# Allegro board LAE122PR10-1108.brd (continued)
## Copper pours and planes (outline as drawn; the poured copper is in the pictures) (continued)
GNDA on GND2: 283.19,30.43 280.19,33.43 280.19,44.92 271.57,53.54 269.5,53.54 265.25,49.29 251.1,49.29 251.1,56.41 249.83,57.68 249.83,61.4 251.1,62.67 251.1,63.05 251.18,63.13 254.2,63.13 254.72,62.61 254.72,57.73 258.41,57.73 258.41,56.99 258.34,56.92 258.34,56.76 259.48,55.62 259.48,53.78 259.85,53.41 262.42,53.41 262.79,53.78 262.79,56.41 262.48,56.72 261.28,56.72 261.14,56.86 261.14,58.26 261.02,58.37 260.93,58.37 260.81,58.49 259.93,58.49 259.93,59.38 260.9,59.38 261.14,59.19 261.14,59.11 261.25,59 261.69,59 262.14,58.56 266.2,58.56 267.34,57.41 273.25,57.41 283.66,47 294.52,47 295.43,46.09 295.4,46 295.39,45.9 295.39,43.5 295.54,43.14 295.9,42.99 299,42.99 299.21,42.91 299.29,42.7 299.29,40.75 299.21,40.54 299,40.46 286.6,40.46 285.9,39.85 286.39,39.07 286.39,33.63 285.9,32.85 286.6,32.24 299,32.24 299.21,32.16 299.29,31.95 299.29,30.43
VCCSA_B+ on TOP (solid shape): 65.17,113.78 65.02,113.63 63.93,113.63 63.78,113.78 63.78,115.02 65.17,115.02
VCCSA_B+ on BOTTOM (solid shape): 65.64,114.54 68.35,114.54 68.35,114.01 67.73,114.01 67.64,113.92 67.64,112.91 67.38,112.66 64.49,112.66 64.49,113.22 63.96,113.22 63.96,112.66 63.73,112.66 63.73,114.96 63.78,115.01 65.17,115.01
VIN_1.8VALW on BOTTOM (solid shape): 170.81,67.3 170.81,66.51 171.27,66.05 171.27,65.75 171.07,65.54 170.38,65.54 168.4,67.52 168.4,67.55 169.11,68.26 169.85,68.26
VIN_1V_PRIM on TOP (solid shape): 161.22,129.49 161.22,129.17 161.41,128.98 161.98,128.98 162.04,128.92 162.04,128.41 161.98,128.34 160.2,128.34 160.08,128.47 160.08,129.49 160.2,129.61 161.09,129.61
VIN_1V_PRIM on BOTTOM (solid shape): 161.19,129.49 161.19,129.11 161.31,128.98 161.95,128.98 162.01,128.92 162.01,128.07 161.92,127.98 161.3,127.98 161.01,127.68 161.01,126.6 160.91,126.5 159.41,126.5 158.58,127.33 158.58,128.53 158.71,128.66 159.6,128.66 159.92,128.98 159.92,129.49 160.04,129.61 161.06,129.61
VIN_1VS_VCCIO on TOP (solid shape): 145.25,131.01 145.25,130.69 145.5,130.44 146.07,130.44 146.07,129.93 146.01,129.87 144.23,129.87 144.17,129.93 144.17,130.95 144.3,131.07 145.18,131.07
VIN_1VS_VCCIO on BOTTOM (solid shape): 145.31,130.95 145.31,130.63 145.44,130.5 146.01,130.5 146.07,130.44 146.07,129.74 145.95,129.61 145.22,129.61 144.98,129.38 144.98,128.03 143.53,128.03 142.71,128.85 142.71,130.06 142.84,130.19 143.72,130.19 144.04,130.5 144.04,130.95 144.17,131.07 145.18,131.07
+AC_IN on TOP (solid shape): 48.89,105.5 48.89,103.8 48.77,103.67 48.18,103.67 47.47,102.96 45.46,102.96 45.44,102.98 45.44,103.44 45.3,103.58 45.3,105.04 45.31,105.05 45.31,105.34 45.62,105.65 48.74,105.65
+AC_IN on TOP (solid shape): outline of 300 points within 29.68,112.42 43.71,120.6
+AC_IN on BOTTOM (solid shape): 47.04,104.47 47.04,103.4 46.75,103.11 45.69,103.11 45.52,102.93 45.52,102.35 45.13,101.97 43.24,101.97 43.15,102.06 43.15,103.36 43.27,103.48 44.26,103.48 45.34,104.56 46.95,104.56
+AC_IN on IN2 (solid shape): 39.9,115.64 41.62,115.64 41.81,115.45 41.81,113.42 41.62,113.23 35.65,113.23 33.3,115.58 32.28,115.58 32.09,115.77 32.09,117.68 32.41,117.99 37.55,117.99
+AC_IN on VCC: 45.4,103.39 39.77,109.02 39.77,115.16 40.52,115.9 45.26,115.9 48.47,112.68 48.47,104.07 47.8,103.39
+BL_PWR_SRC on TOP (solid shape): 48.25,128.5 48.25,128.05 46.51,126.31 46.51,122.12 46.38,121.99 45.11,121.99 44.98,122.12 44.98,126.17 45.08,126.27 45.08,127.16 47.03,129.11 47.64,129.11
+BL_PWR_SRC on TOP (solid shape): 58.02,133.22 58.94,133.22 59.3,132.85 60.79,132.85 60.98,132.66 60.98,131.9 60.5,131.42 58.89,131.42 58.59,131.71 57.68,131.71 57.2,132.19 56.52,132.19 56.43,132.28 56.43,133.76 56.54,133.87 57.36,133.87
+BL_PWR_SRC on BOTTOM (solid shape): 60.37,133.28 60.37,132 60.54,131.84 60.54,131.39 60.41,131.27 59.12,131.27 58.89,131.5 58.89,131.79 59.13,132.03 59.13,133.28 59.21,133.36 60.3,133.36
+CHARGER_SRC on TOP (solid shape): 47.97,79.39 49.24,79.39 49.55,79.07 49.55,72.78 49.11,72.34 47.01,72.34 46.63,71.96 46.63,71.38 46.19,71.38 46.19,75.51 45.81,75.89 45.81,79.83 45.55,80.08 45.55,80.67 45.59,80.71 46.65,80.71
+CHARGER_SRC on BOTTOM (solid shape): 49.24,84.02 48.66,84.02 48.66,81.99 49.24,81.99 49.24,80.21 49.93,79.51 50.89,79.51 50.89,73.54 50.82,73.48 46.06,73.48 45.81,73.73 45.81,79.83 45.55,80.08 45.55,84.15 45.81,84.4 48.37,84.4 48.47,84.5 49.24,84.5
+DC_IN on BOTTOM (solid shape): 46.89,121.11 47.33,120.66 47.33,118.5 47.23,118.4 43.59,118.4 43.53,118.4 43.46,118.4 42.63,118.4 42.63,118.38 41.87,118.38 41.74,118.5 41.74,119.26 41.81,119.33 42.51,119.33 42.89,119.71 42.89,121.17 43.39,121.68 46.89,121.68
+DC_IN_SS on BOTTOM (solid shape): 52.78,118.71 52.78,117.33 52.63,117.18 49.58,117.18 48.94,116.55 48.94,113.24 48.77,113.07 44.78,113.07 44.5,113.25 44.17,113.16 44.13,113.13 43.89,113.37 43.89,115.4 44.17,115.68 44.17,116.32 44.83,116.98 44.83,117.59 45.01,117.77 47.55,117.77 48.7,118.92 52.57,118.92
+DCIN_JACK on BOTTOM (solid shape): 41.92,121.74 42.01,121.71 42.09,121.69 42.11,121.69 42.31,121.49 42.31,119.84 42.06,119.58 41.74,119.58 41.49,119.33 41.49,118.44 41.3,118.25 39.27,118.25 39.09,118.07 36.71,118.07 36.47,118.31 36.47,121.4 36.82,121.74 41.84,121.74
+EC_DEBUG_VCC on BOTTOM (solid shape): 289.57,127.46 289.95,127.46 290.61,126.8 291.11,126.8 291.32,126.59 291.32,126.29 291.23,126.2 289.93,126.2 289.74,126.39 289.19,126.39 288.86,126.73 288.86,127.37 288.95,127.46 289.57,127.46
+EDP_VDD on TOP (solid shape): 67.97,126.95 67.97,124.92 67.65,124.6 66.7,124.6 66.52,124.78 66.52,125.61 65.86,126.27 65.86,127.71 67.21,127.71
+LCDVDD on TOP (solid shape): 66.19,132.26 66.19,130.95 65.95,130.7 65.95,128.29 65.68,128.03 65.68,127.46 65.11,127.46 65.11,126.95 65.68,126.95 65.68,126.69 64.6,126.69 64.41,126.88 64.41,131.14 64.86,131.59 64.86,132.41 66.04,132.41
+LCDVDD on BOTTOM (solid shape): 66.38,133.3 66.38,132.03 66.57,131.84 66.57,131.2 66.13,130.76 66.13,129.74 66,129.61 64.79,129.61 64.67,129.74 64.67,131.58 64.92,131.84 65.43,131.84 65.62,132.03 65.62,133.3 65.68,133.36 66.32,133.36
+PBATT on TOP (solid shape): outline of 107 points within 170.2,55.26 177.96,60.78
+PWR_SRC on TOP (solid shape): 44.54,123.33 44.54,121.93 44.28,121.68 42.05,121.68 41.89,121.84 41.89,122.24 41.88,122.33 41.85,122.43 41.85,123.05 41.92,123.13 43.57,123.13 43.9,123.45 44.41,123.45
+PWR_SRC on TOP (solid shape): 171.22,53.35 171.22,52.41 170.69,52.41 170.67,52.39 170.65,52.38 170.34,52.03 170.65,51.68 170.67,51.67 170.69,51.65 171.14,51.65 171.17,51.62 171.17,50.19 170.84,49.86 164.74,49.86 164.43,50.18 164.43,52.75 165.34,53.67 170.9,53.67
+PWR_SRC on TOP (solid shape): 71.59,81.1 74.76,81.1 75.59,80.27 75.59,76.27 75.14,75.83 73.56,75.83 72.32,77.06 64.34,77.06 63.69,76.41 63.69,74.28 63.51,74.11 63.37,74.01 63.27,73.87 63.27,73.86 62.57,73.16 62.57,66.75 62.13,66.3 58.7,66.3 58.7,65.35 58.25,65.35 58.25,69.61 58.82,70.18 58.83,70.33 58.83,76.78 59.02,76.97 59.02,80.08 60.48,81.54 71.14,81.54
+PWR_SRC on BOTTOM (solid shape): 181.36,50.94 183.9,50.94 184,50.84 184,49.84 184.25,49.59 184.25,49.54 184.05,49.34 180.16,49.34 179.98,49.52 179.98,50.31 180.62,50.94 181.36,50.94
+PWR_SRC on BOTTOM (solid shape): 39.01,130.57 39.01,129.75 38.75,129.13 39.36,128.85 39.39,128.86 43.75,124.49 43.75,122.28 43.46,121.99 41.94,121.99 41.84,122.09 41.85,122.12 41.86,122.29 41.81,122.46 41.81,124.09 39.14,126.76 39.14,127.52 37.87,128.79 37.87,130.5 38.06,130.69 38.89,130.69
+PWR_SRC on BOTTOM (solid shape): outline of 1686 points within 57.97,49.86 169,82.82
+PWR_SRC on IN1 (solid shape): outline of 167 points within 164.36,49.34 182.47,52.87
+PWR_SRC on IN2 (solid shape): 45.44,122.31 45.44,121.04 45.27,120.86 42.26,120.86 41.87,121.26 41.87,122.31 42,122.44 45.31,122.44
+PWR_SRC on IN2 (solid shape): 58.32,119.24 58.32,118.53 58.71,118.13 58.71,117.44 58.52,117.24 57.28,117.24 56.68,117.84 56.68,118.69 56.46,118.91 56.46,119.87 56.59,120 57.55,120
+PWR_SRC on IN3 (solid shape): 58.74,118.06 58.74,116.52 58.58,116.37 57.24,116.37 57.24,118.06 57.36,118.18 58.61,118.18
+PWR_SRC on IN3 (solid shape): 58.76,81.99 58.76,80.4 58.57,80.21 57.43,80.21 56.86,80.78 56.86,82.31 57.43,82.88 57.87,82.88
+PWR_SRC on IN3 (solid shape): outline of 190 points within 164.36,49.34 182.47,52.08
+PWR_SRC_AC on TOP (solid shape): 54.13,84.15 54.13,80.53 53.81,80.21 50.63,80.21 50.44,80.4 50.44,82.93 50.98,82.93 51.33,83.28 50.98,83.64 50.44,83.64 50.44,84.34 50.57,84.47 53.81,84.47
+PWR_SRC_AC on BOTTOM (solid shape): 49.72,84.4 53.49,84.4 54,83.89 54,80.53 53.68,80.21 49.81,80.21 49.43,80.59 49.43,84.5 49.62,84.5
+REGCTL_PNP10 on TOP (solid shape): 246.58,123.43 246.58,122.08 246.91,121.75 246.91,121.09 246.78,120.97 246.3,120.97 246.18,121.09 246.18,121.57 246.25,121.77 246.18,121.96 246.18,122.16 246.38,122.36 246.38,123.43 246.43,123.48 246.53,123.48
+REGCTL_PNP10 on BOTTOM (solid shape): 252.25,125.32 252.25,124.28 251.8,123.84 250.85,123.84 250.51,124.18 250.51,125.26 250.67,125.42 252.14,125.42
+REGCTL_PNP10 on IN3 (solid shape): 251.61,124.55 251.61,123.76 250.42,122.57 247.86,122.57 247.1,121.8 247.1,121.04 246.91,120.85 246.15,120.85 245.83,121.17 245.83,122.57 247.31,124.04 250.08,124.04 250.22,124.18 250.23,124.18 250.4,124.28 250.5,124.45 250.5,124.47 250.76,124.72 251.43,124.72
+RTC_CELL on TOP (solid shape): outline of 308 points within 119.76,89.76 124.68,97.88
+SDC_IN on TOP (solid shape): 52.35,111.45 52.35,109.48 52.03,109.17 50.25,109.17 50.06,109.36 50.06,109.93 49.87,110.12 48.79,110.12 48.66,109.99 48.66,109.36 47.2,109.36 47.14,109.42 47.14,111.2 47.97,112.02 51.78,112.02
+SDC_IN on TOP (solid shape): 51.33,86.43 51.33,84.91 51.14,84.72 50.19,84.72 49.43,83.96 49.43,83.67 48.89,83.67 48.86,83.64 48.85,83.64 48.54,83.28 48.85,82.93 48.86,82.93 48.89,82.9 49.32,82.9 49.35,82.87 49.35,82.18 46.7,82.18 45.81,83.07 45.81,86.12 46.32,86.62 51.14,86.62
+SDC_IN on BOTTOM (solid shape): 52.75,116.39 52.75,111.57 51.95,111.57 51.59,111.2 51.59,110.4 51.01,109.83 51.01,105.23 47.71,105.23 47.71,106.42 47.7,106.44 47.7,106.79 47.42,107.07 46.23,107.07 45.74,106.59 45.21,106.59 44.98,106.82 44.98,107.63 45.21,107.86 46,107.86 46.23,108.09 46.23,108.6 45.97,108.85 44.91,108.85 44.7,108.65 44.04,108.65 44.04,109.18 44.12,109.26 45.83,109.26 46.06,109.48 46.06,110.06 46.44,110.44 46.44,111.2 46.23,111.42 46.23,112.32 46.32,112.41 48.73,112.41 49.43,113.1 49.43,116.41 49.49,116.47 52.68,116.47
+SDC_IN on IN2 (solid shape): outline of 2338 points within 45.68,84.4 56.79,111.9
+SDREG2 on TOP (solid shape): 279,67.88 279.09,67.79 279.09,67.13 279.02,67.05 278.52,67.05 277.77,66.3 277.77,66.23 277.71,66.16 276.93,66.16 276.87,66.23 276.87,66.31 276.93,66.38 277.09,66.38 277.96,67.26 277.96,67.63 278.22,67.88 278.81,67.88
+TBTA_VBUS on TOP (solid shape): 24.15,116.79 24.15,114.06 23.84,113.74 23.39,113.74 23.14,113.49 23.14,112.91 20.47,112.91 19.52,113.87 16.79,113.87 16.41,114.25 16.41,116.6 16.72,116.91 24.03,116.91
+TBTA_VBUS on TOP (solid shape): 7.29,108.57 8.38,108.57 8.47,108.66 9.76,108.66 9.85,108.57 9.85,108.24 9.78,108.16 8.43,108.16 8.36,108.24 7.16,108.24 7.09,108.16 6.4,108.16 6.27,108.29 6.27,108.67 6.45,108.85 7.01,108.85
+TBTA_VBUS on TOP (solid shape): 7.14,106.06 8.38,106.06 8.47,106.14 9.5,106.14 9.57,106.07 9.57,105.73 9.5,105.65 8.43,105.65 8.36,105.73 7.16,105.73 6.88,105.45 6.42,105.45 6.3,105.57 6.3,106.03 6.42,106.16 7.03,106.16
+TBTA_VBUS on BOTTOM (solid shape): 10.06,105.93 10.06,104.91 9.23,104.91 8.48,105.66 8.48,105.99 8.6,106.11 9.88,106.11
+TBTA_VBUS on IN2 (solid shape): outline of 315 points within 6.32,105.42 22.82,116.6
+TBTA_VBUS on VCC: 6.32,105.42 6.32,108.91 7.88,108.91 8.66,109.7 8.66,111.22 11.43,113.99 13.15,113.99 14.82,115.67 14.82,116.93 22.25,116.93 22.25,114.42 21.95,114.12 20.87,114.12 16.62,109.87 13.89,109.87 12.41,108.38 12.41,105.4 12.3,105.29 7.64,105.29 7.52,105.42
+TBTA_VBUS_1 on TOP (solid shape): 29.11,118.86 29.61,118.35 29.61,113.17 29.36,112.91 27.5,112.91 27.49,112.92 27.13,112.92 27.13,112.91 25.8,112.91 25.8,113.55 25.68,113.68 25.17,113.68 25.04,113.8 25.04,116.85 25.23,117.04 25.32,117.04 26.12,117.84 26.12,121.04 26.31,121.23 29.11,121.23
+TBTA_VBUS_1 on BOTTOM (solid shape): 17.55,79.35 17.55,75.28 17.3,75.03 16.51,75.03 16.48,75.07 16.47,75.07 16.22,75.32 16.22,77.86 15.9,78.18 15.9,79.64 16.06,79.81 17.09,79.81
+TBTA_VBUS_1 on TOP: 29.64,77 29.49,77 29.23,76.74 29.23,76.26 29.13,76.16 28.29,76.16 28.22,76.24 28.22,77.61 28.85,78.24 29.23,78.24 29.36,78.37 29.36,78.56 29.42,78.62 29.68,78.62 29.81,78.75 29.81,79.07 29.87,79.13 30.14,79.13 30.25,79.02 30.25,78.75 30.38,78.62 30.57,78.62 30.63,78.56 30.63,77.99
+TBTA_VBUS_1 on IN1: 16.03,79.83 16.34,79.83 19.71,76.46 19.71,75.39 19.96,75.13 21.23,75.13 22.88,76.78 26,76.78 27.27,78.05 29.87,78.05 30.19,77.73 30.19,76.46 29.11,75.39 26.82,75.39 26.12,74.69 23.58,74.69 22.76,73.86 19.39,73.86 15.9,77.35 15.9,79.7
+TBTA_VBUS_1 on IN2: 29.61,79.13 28.98,79.77 16.09,79.77 15.84,79.51 15.84,76.85 18.06,74.62 28.09,74.62 30,76.53 30,77.87 30.31,78.19 33.74,78.19 34.1,78.55 34.56,78.55 34.69,78.69 34.69,79 34.57,79.13
+TBTA_VBUS_1 on IN3: 23.2,107.2 22.47,107.93 22.47,116.37 22.88,116.79 25.3,116.79 26.06,117.55 26.63,117.55 26.76,117.42 26.76,111.64 27.81,110.6 27.81,107.87 29.23,106.44 29.23,100.72 26.18,97.67 21.29,97.67 17.99,94.37 17.99,78.43 17.49,77.93 15.58,77.93 14.95,78.56 14.95,96.18 19.08,100.32 22.37,100.32 23.2,101.14
+USB_EX2_PWR on TOP (solid shape): 19.65,67.45 19.65,65.35 15.64,65.35 15.33,65.67 15.33,67.19 15.45,67.31 17.76,67.31 18.02,67.57 19.52,67.57
+USB_EX2_PWR on BOTTOM (solid shape): 20.09,58.11 20.09,56.4 20.28,56.21 20.28,55.38 20.15,55.26 18.44,55.26 18.25,55.45 18.25,57.92 18.5,58.18 20.03,58.18
+USB_EX2_PWR on IN2 (solid shape): 19.96,67 19.96,55.83 19.65,55.51 18.18,55.51 17.93,55.76 17.93,64.78 17.36,65.35 15.71,65.35 15.33,65.73 15.33,66.18 16.46,67.31 17.81,67.31 17.95,67.45 19.52,67.45
+UZ12_TPM on BOTTOM (solid shape): 162.46,115.96 162.46,112.61 161.94,112.09 160.76,112.09 160.69,112.15 160.69,113.13 161.07,113.51 161.07,115.29 161.18,115.4 161.18,116.01 161.29,116.11 162.3,116.11
+VCHGR on TOP (solid shape): 177.06,54.56 177.06,53.46 177.95,52.57 177.95,51.24 174.85,51.24 174.49,50.89 172.38,50.89 172.24,51.03 172.24,51.67 172.78,51.67 173.14,52.03 172.78,52.39 172.24,52.39 172.24,53.48 172.49,53.73 174.52,53.73 174.78,53.99 174.78,54.56 174.9,54.68 176.93,54.68
+VHDMI_VCC on TOP (solid shape): 15.14,89.29 16.09,89.29 16.22,89.16 16.22,88.47 16.34,88.34 17.04,88.34 17.04,87.83 16.41,87.83 16.15,88.09 14.69,88.09 13.59,89.19 12.88,89.19 12.7,89.37 12.7,89.93 13.1,90.33 14.1,90.33
+VHDMI_VCC on BOTTOM (solid shape): 17,89.62 17.52,89.62 18.06,89.09 18.59,89.09 18.74,88.94 18.74,88.15 18.57,87.97 18.03,87.97 17.54,88.47 16.47,88.47 16.22,88.21 15.77,88.21 15.64,88.34 15.64,90.36 15.73,90.44 16.18,90.44
BOOT1_ISL88738 on TOP (solid shape): 57.48,60.92 57.2,60.92 56.69,60.41 56.69,59.83 56.82,59.7 56.82,58.68 56.77,58.63 56.67,58.63 56.62,58.68 56.62,59.47 56.34,59.75 56.34,60.82 56.62,61.1 56.62,61.53 57.48,61.53
BOOT2_ISL88738 on TOP (solid shape): 61.11,56.4 60.48,56.4 60.25,56.63 59.31,56.63 59.21,56.73 58.16,56.73 58.11,56.78 58.11,56.88 58.16,56.93 60.12,56.93 60.48,57.29 61.11,57.29
BST_3V on BOTTOM (solid shape): 155.47,74.28 155.47,73.52 155.85,73.14 156.72,73.14 156.82,73.04 156.82,72.22 156.79,72.2 155.95,72.2 155.22,72.93 155.22,74.26 155.29,74.33 155.42,74.33
BST_5V on BOTTOM (solid shape): 185.95,54.47 185.95,53.96 186.84,53.07 186.84,51.95 185.95,51.95 185.89,52.02 185.89,53.49 185.7,53.68 185.7,54.44 185.77,54.52 185.9,54.52
BST_+1VALWP on TOP (solid shape): 154.38,85.47 154.38,83.37 153.77,83.37 153.3,83.84 153.3,85.47 153.45,85.63 154.22,85.63
BST_+1VALWP on BOTTOM (solid shape): 154.41,85.41 154.41,84.42 154.35,84.36 153.39,84.36 153.29,84.47 153.29,85.45 153.43,85.59 154.23,85.59
BST_+1VALWP_C on TOP (solid shape): 156.75,83.41 155.16,83.41 155.16,84.3 156.75,84.3
CORE_SNUB on BOTTOM (solid shape): 59.47,104.39 59.47,101.57 59.42,101.52 58.37,101.52 58.32,101.57 58.32,104.39 58.44,104.52 59.33,104.52
CORE_SW on BOTTOM (solid shape): 64.06,109.14 64.06,107.81 61.54,107.81 61.54,106.97 64.06,106.97 64.06,104.81 62.16,102.92 62.16,101.59 62.08,101.51 60.07,101.51 59.71,101.87 59.71,106.12 59.36,106.46 58.93,106.46 58.57,106.82 58.23,106.82 58.16,106.88 58.16,109.18 58.22,109.23 63.97,109.23
CPU_B+ on TOP (solid shape): 54.82,110.13 54.82,106.31 55.27,105.87 55.27,103.01 55.14,102.88 53.43,102.88 53.17,103.13 53.17,110.01 53.41,110.24 54.71,110.24
CPU_B+ on TOP (solid shape): 64.35,87.26 65.75,87.26 65.75,87.83 66.51,87.83 66.76,87.58 66.76,83.49 66.6,83.32 63.8,83.32 63.65,83.48 63.65,87.58 63.9,87.83 64.35,87.83
CPU_B+ on BOTTOM (solid shape): 64.98,112.34 64.98,111.45 64.86,111.33 63.59,111.33 63.46,111.45 63.46,112.34 63.59,112.47 64.86,112.47
CPU_B+ on BOTTOM (solid shape): 55.55,109.21 55.55,104.68 55.27,104.4 55.27,103.01 55.14,102.88 53.68,102.88 53.17,103.39 53.17,108.47 53.43,108.72 54.13,108.72 54.63,109.23 55.52,109.23
CPU_B+ on BOTTOM (solid shape): 67.46,88.21 67.46,83.32 66.83,82.69 59.84,82.69 59.59,82.94 59.59,85.48 59.84,85.74 61.14,85.74 61.62,86.22 61.62,88.02 62.25,88.66 67.02,88.66
CPU_B+ on VCC: 63.12,83.32 56.92,89.52 56.92,92.57 54.89,94.6 54.89,97.72 53.62,98.99 53.62,102.99 53.17,103.43 53.17,106.9 58.74,112.47 64.86,112.47 64.86,109.21 63.46,107.81 63.46,97 69.49,90.96 69.49,85.97 66.85,83.32 ; 1 cut-out
EN_1.8VALW on BOTTOM (solid shape): 175.54,66.3 175.54,66.23 174.34,65.03 173.94,65.03 173.51,65.47 173.51,67.52 173.91,67.93
GPU_B+ on TOP (solid shape): 67.52,88.4 67.14,88.02 62.38,88.02 62.13,88.28 62.13,90.12 62.32,90.31 64.16,90.31 64.35,90.5 64.35,90.56 67.52,90.56
GPU_B+ on BOTTOM (solid shape): 67.77,90.83 67.77,89.16 67.54,88.94 61.53,88.94 61.16,89.3 61.16,91.1 61.19,91.12 67.47,91.12
GT_SNUB1 on TOP (solid shape): 64.48,95.26 63.65,95.26 63.27,94.88 61.56,94.88 61.56,95.9 64.48,95.9
GT_SW1 on TOP (solid shape): 63.21,96.72 63.02,96.53 61.81,96.53 61.56,96.78 61.56,98.56 63.21,98.56
GT_SW1 on BOTTOM (solid shape): 64.39,100.62 64.39,99.32 64.36,99.3 61.85,99.3 61.85,98.46 64.36,98.46 64.36,94.11 63.97,93.71 61.19,93.71 61.19,95.54 60.53,96.2 60.53,100.44 61.12,101.04 63.97,101.04
HDMI_OB on TOP (solid shape): 18.12,80.02 18.38,79.77 18.38,78.62 18.18,78.43 17.61,78.43 17.42,78.62 17.42,87.13 17.55,87.26 18.12,87.26
INT_SPK_L+ on TOP (solid shape): 279.61,24.08 280.12,24.08 280.12,22.36 279.61,22.36 279.49,22.49 279.49,22.81 278.53,23.76 278.53,24.65 279.04,24.65
INT_SPK_L+ on TOP (solid shape): 265.35,60.95 265.35,59.95 262.91,59.95 262.79,59.83 261.33,59.83 261.12,60.03 259.97,60.03 259.92,60.08 259.92,60.18 259.97,60.23 262.63,60.23 263.37,60.97 265.33,60.97
INT_SPK_L- on TOP (solid shape): 279.68,26.11 280.06,26.11 280.12,26.05 280.12,24.39 279.61,24.39 279.55,24.46 279.55,24.78 278.66,25.66 278.66,26.24 278.92,26.49 279.3,26.49
INT_SPK_L- on TOP (solid shape): 265.17,61.1 263.29,61.1 262.58,60.39 260.88,60.39 260.83,60.44 259.94,60.44 259.92,60.46 259.92,60.59 259.97,60.64 262.23,60.64 263.7,62.11 263.83,62.11 263.83,62.11 265.17,62.11
INT_SPK_R+ on TOP (solid shape): 279.97,21.62 279.97,20.45 279.85,20.33 278.7,20.33 278.57,20.46 278.57,21.54 278.76,21.73 279.86,21.73
INT_SPK_R+ on TOP (solid shape): 262.71,62.19 262.71,61.95 262.52,61.76 261.74,61.76 261.2,61.22 259.97,61.22 259.92,61.28 259.92,61.4 259.97,61.45 260.91,61.45 261.75,62.29 262.61,62.29
INT_SPK_R+ on IN1 (solid shape): 278.98,22.62 280,21.6 280,21.35 279.87,21.22 278.92,21.22 277.96,22.17 277.96,23.12 278.98,23.12
INT_SPK_R+ on IN1 (solid shape): 263.63,61.78 263.63,61.78 263.63,61.68 261.72,61.68 261.62,61.78 261.62,61.89 261.62,61.89 261.62,62.6 261.72,62.7 263.63,62.7
INT_SPK_R- on TOP (solid shape): 279.97,19.44 279.97,18.3 278.7,18.3 278.57,18.43 278.57,18.93 278.32,19.19 278.32,19.57 278.45,19.7 279.72,19.7
INT_SPK_R- on TOP (solid shape): 262.51,61.45 262.51,61.2 262.13,60.82 259.97,60.82 259.92,60.87 259.92,61 259.97,61.05 261.31,61.05 261.8,61.53 262.43,61.53
INT_SPK_R- on IN1 (solid shape): 279.49,20.27 279.49,19.38 279.3,19.19 278.6,19.19 278.41,19.38 278.41,20.65 278.6,20.84 278.92,20.84
INT_SPK_R- on IN1 (solid shape): 263.27,60.49 261.69,60.49 261.47,60.72 261.47,61.4 261.57,61.5 263.27,61.5
INT_SPKR_L+ on TOP (solid shape): 281.52,23.1 281.52,22.31 281.51,22.31 281.39,22.2 280.55,22.2 280.38,22.38 280.38,23.14 280.5,23.26 281.35,23.26
INT_SPKR_L+ on BOTTOM (solid shape): 283.11,22.31 283.08,22.29 281.96,22.29 281.89,22.21 281.13,22.21 281.02,22.31 281.02,23.18 281.15,23.3 283.11,23.3
INT_SPKR_L- on TOP (solid shape): 281.52,25.16 281.52,24.37 281.51,24.37 281.39,24.26 280.55,24.26 280.38,24.43 280.38,25.2 280.5,25.32 281.35,25.32
INT_SPKR_L- on BOTTOM (solid shape): 283.11,25.23 283.11,24.27 283.06,24.22 281.15,24.22 281.02,24.34 281.02,25.13 281.18,25.28 283.06,25.28
INT_SPKR_R+ on TOP (solid shape): 282.04,21.05 282.04,20.33 281.86,20.15 280.46,20.15 280.33,20.27 280.33,21.1 280.45,21.22 281.87,21.22
INT_SPKR_R+ on BOTTOM (solid shape): 283.61,21.09 283.61,20.2 283.55,20.14 281.2,20.14 281.01,20.33 281.01,21.16 281.14,21.28 283.42,21.28
INT_SPKR_R- on TOP (solid shape): 281.52,19.02 281.52,18.24 281.51,18.24 281.39,18.12 280.45,18.12 280.33,18.24 280.33,19.06 280.45,19.19 281.35,19.19
INT_SPKR_R- on BOTTOM (solid shape): 283.25,19.28 283.25,18.33 283.03,18.11 281.2,18.11 281.01,18.3 281.01,19.06 281.14,19.19 281.71,19.19 281.9,19.38 283.15,19.38
LG1_ISL88738 on TOP (solid shape): 42.44,71.64 42.44,71.19 42.57,71.07 42.57,70.56 42.44,70.43 41.55,70.43 41.43,70.56 41.43,71.51 41.74,71.83 42.25,71.83
LG1_ISL88738 on TOP (solid shape): 58.98,60.08 58.98,59.65 57.96,58.63 57.89,58.63 57.81,58.71 57.81,59.47 58.55,60.21 58.85,60.21
LG1_ISL88738 on IN3 (solid shape): 42.54,70.78 42.54,69.15 42.52,69.12 41.96,69.12 41.45,69.63 41.45,70.8 41.58,70.93 42.39,70.93
LG1_ISL88738 on IN3 (solid shape): 59.74,60.36 58.65,59.27 58.27,59.27 58.14,59.4 58.14,59.7 58.72,60.29 58.72,61.07 59.74,61.07
LG2_ISL88738 on TOP (solid shape): 60.12,58.76 60.12,58.43 60.02,58.33 59.61,58.33 59.23,57.95 58.16,57.95 58.11,58 58.11,58.1 58.16,58.15 58.95,58.15 59.64,58.84 60.04,58.84
LINE1_L on TOP (solid shape): 254.71,58.99 254.71,58.89 254.66,58.84 253.9,58.84 253.69,58.63 253.69,57.57 252.98,56.86 252.13,56.86 252.13,57.75 253.07,57.75 253.29,57.97 253.29,58.63 253.69,59.04 254.66,59.04
LINE1_R on TOP (solid shape): 254.74,59.4 254.74,59.29 254.66,59.22 253.64,59.22 253.13,58.71 253.13,58.18 253.01,58.05 252.17,58.05 252.17,58.94 252.96,58.94 253.47,59.45 254.68,59.45
LX1_ISL88738 on TOP (solid shape): 45.49,71.26 45.87,70.88 46.51,70.88 47.33,70.05 47.33,67.32 47.14,67.13 43.58,67.13 42.82,67.89 42.82,75.39 45.49,75.39
LX1_ISL88738 on TOP (solid shape): 58.7,60.56 57.63,59.5 57.63,58.68 57.58,58.63 57.48,58.63 57.43,58.68 57.43,59.93 57.81,60.31 57.81,61.5 57.83,61.53 58.7,61.53
LX1_ISL88738 on BOTTOM (solid shape): 47.27,71.96 47.27,66.69 46.57,65.99 42.31,65.99 42.25,66.05 42.25,69.99 42.38,70.11 42.57,70.11 42.82,70.37 42.82,72.46 43.08,72.72 46.51,72.72
LX1_ISL88738 on IN1 (solid shape): 47.32,70.75 46.89,70.75 46.35,70.22 45.52,70.22 45.39,70.34 45.39,71.18 45.97,71.77 47.32,71.77
LX1_ISL88738 on IN1 (solid shape): 58.7,61.83 58.7,60.51 57.86,59.68 57.61,59.68 57.48,59.8 57.48,60.06 57.73,60.31 57.73,61.83 57.81,61.91 58.62,61.91
LX2_ISL88738 on TOP (solid shape): 57.62,69.72 57.62,65.8 56.22,64.4 56.22,62.75 55.21,62.75 55.21,64.4 54.95,64.65 54.95,69.61 55.23,69.89 57.45,69.89
LX2_ISL88738 on TOP (solid shape): 61.11,57.62 60.3,57.62 60.2,57.72 59.66,57.72 59.49,57.54 58.16,57.54 58.11,57.59 58.11,57.69 58.16,57.75 59.23,57.75 59.69,58.2 60.2,58.2 60.48,58.48 61.11,58.48
LX2_ISL88738 on BOTTOM (solid shape): 56.68,69.91 57.17,69.91 57.55,69.53 57.55,65.75 57.4,65.59 54.27,65.59 53.94,65.92 51.52,65.92 51.46,65.99 51.46,70.24 51.71,70.5 56.09,70.5
LX_1.8VALW on BOTTOM (solid shape): 175.41,64.34 175.41,64.21 172.93,61.73 172.49,61.73 172.05,62.18 172.05,62.3 172.44,62.7 172.44,63.38 171.88,63.94 171.88,64.17 172.3,64.59 172.68,64.59 173.19,64.08 173.76,64.08 174.65,64.97 174.78,64.97
LX_1V_PRIM on BOTTOM (solid shape): 155.4,129.47 155.4,129.25 155.34,129.2 155.34,128.79 155.47,128.66 156.31,128.66 156.39,128.59 156.39,127.98 156.31,127.9 155.47,127.9 155.32,127.75 155.32,127.18 154.84,126.69 154.01,126.69 153.95,126.76 153.95,129.42 154.13,129.6 155.27,129.6
LX_1VS_VCCIO on BOTTOM (solid shape): 139.66,131.84 139.66,131.07 139.47,130.88 139.47,130.31 139.6,130.19 140.44,130.19 140.51,130.11 140.51,129.5 140.44,129.42 138.2,129.42 138.07,129.55 138.07,131.96 138.14,132.03 139.47,132.03
LX_3V on BOTTOM (solid shape): 153.34,74.61 153.34,74.48 153.24,74.38 153.24,73.77 153.08,73.62 152.63,73.62 152.25,74 152.25,74.39 152.53,74.67 153.27,74.67
LX_3V on BOTTOM (solid shape): 159.84,73.59 159.35,73.1 159.35,71.32 158.33,71.32 158.33,72.59 158.2,72.72 157.12,72.72 157.12,73.16 157,73.29 156.01,73.29 155.73,73.57 155.73,74.33 155.57,74.48 155.57,75.07 155.64,75.13 157.44,75.13 157.69,75.39 157.69,78.33 157.71,78.34 159.84,78.34
LX_3V on IN1 (solid shape): 153.41,74.48 153.69,74.34 153.98,74.48 154.93,74.48 155.22,74.33 155.51,74.48 157.02,74.48 157.12,74.38 157.12,73.67 157.02,73.57 152.58,73.57 152.25,73.9 152.25,74.38 152.35,74.48
LX_5V on TOP (solid shape): 188.62,53.54 182.84,53.54 182.6,53.78 182.6,54.35 182.8,54.56 183.6,54.56 183.79,54.37 186.33,54.37 187.16,55.19 188.62,55.19
LX_5V on BOTTOM (solid shape): 183.82,54.8 183.82,54.67 183.6,54.46 183.6,54.11 183.48,53.99 182.7,53.99 182.6,54.09 182.6,54.46 183.01,54.86 183.75,54.86
LX_5V on BOTTOM (solid shape): 190.84,56.82 190.84,53.54 189.25,51.95 187.16,51.95 187.16,53.03 186.21,53.99 186.21,54.52 186.05,54.67 186.05,55.26 186.12,55.32 187.92,55.32 188.17,55.57 188.17,57.01 190.65,57.01
LX_DDR on TOP (solid shape): 68.48,67.64 68.48,65.86 66.83,65.86 66.83,67.63 66.97,67.77 68.35,67.77
LX_DDR on BOTTOM (solid shape): 68.5,68.63 69.18,67.96 69.18,64.72 69.11,64.65 64.48,64.65 64.1,65.03 64.1,67.61 64.13,67.65 66.27,67.65 67.21,68.59 67.21,70.24 68.5,70.24
Net_56 on BOTTOM (solid shape): 282.2,39.4 278.1,39.4 278.1,47 282.2,47
Net_57 on BOTTOM (solid shape): 206.1,65.55 192,65.55 192,68.15 206.1,68.15
PBATT+_C on TOP (solid shape): 169.95,58.51 169.95,58.01 170.11,57.85 170.71,57.85 172.1,56.46 174.08,56.46 174.46,56.08 174.46,54.11 174.33,53.99 167.85,53.99 167.09,54.75 167.09,56.97 167.28,57.16 167.92,57.16 168.04,57.29 168.04,58.41 168.54,58.9 169.55,58.9
PBATT+_C on BOTTOM (solid shape): 174.14,58.11 174.14,57.48 172.24,55.57 168.84,55.57 168.04,56.37 168.04,58.94 168.43,59.32 170.08,59.32 171.35,60.59 171.66,60.59
RING2 on TOP (solid shape): 252.14,62.05 252.89,62.05 253.9,61.05 254.66,61.05 254.74,60.97 254.74,60.87 254.68,60.82 253.62,60.82 253.31,61.12 252.5,61.12 252.04,61.58 251.56,61.58 251.56,62.14 252.06,62.14
RING2 on BOTTOM (solid shape): 285.27,46.18 285.27,45.35 285.14,45.22 284.25,45.22 284.12,45.35 284.12,46.18 284.25,46.3 285.14,46.3
RING2 on IN3 (solid shape): 253.19,61.94 254.05,61.94 254.53,61.45 254.53,60.51 253.52,60.51 253.52,60.92 253.31,61.12 252.47,61.12 252.32,61.28 252.32,61.83 252.47,61.99 253.19,61.99
RING2 on IN3 (solid shape): 284.3,46.29 284.48,46.29 284.61,46.16 284.61,45.38 284.48,45.25 283.89,45.25 283.08,46.06 283.08,46.59 283.28,46.8 283.79,46.8
RING2_R on BOTTOM (solid shape): 292.62,46.25 292.62,45.5 292.92,45.2 293.46,45.2 293.71,44.94 293.71,43.57 295.74,41.54 295.74,40.71 294.79,40.71 294.47,41.03 294.47,41.22 292.7,43 292.7,44.52 291.17,46.05 289.2,46.05 288.5,45.35 285.71,45.35 285.61,45.45 285.61,46.16 285.69,46.24 287.42,46.24 288.25,47.06 291.81,47.06
SA_SNUB on TOP (solid shape): 67.66,115.61 66.64,114.58 66.64,113.68 65.62,113.68 65.62,115.33 66.5,115.33 67,115.83 67,116.55 67.66,116.55
SA_SW on TOP (solid shape): 69.29,115.76 69.29,113.68 68.3,113.68 68.3,115.76 68.45,115.91 69.14,115.91
SA_SW on TOP (solid shape): 63.5,113.47 63.5,113.09 62.89,112.48 62.25,112.48 62.25,113.35 62.86,113.35 63.12,113.6 63.37,113.6
SA_SW on BOTTOM: 69.78,116.94 71.92,116.94 71.94,116.91 71.94,114.1 71.78,113.93 68.73,113.93 68.58,114.08 68.58,114.74 68.45,114.87 65.81,114.87 65.81,115.89 68.73,115.89
SLEEVE on TOP (solid shape): 252.42,60.95 253.24,60.95 253.54,60.64 254.68,60.64 254.74,60.59 254.74,60.49 254.66,60.41 252.98,60.41 252.93,60.46 251.66,60.46 251.56,60.56 251.56,61.25 252.12,61.25
SLEEVE on BOTTOM (solid shape): 285.27,44.97 285.27,44.14 285.14,44.02 284.25,44.02 284.12,44.14 284.12,44.97 284.25,45.1 285.14,45.1
SLEEVE on IN3 (solid shape): 253.26,60.82 253.26,59.73 252.25,59.73 252.25,60.79 252.37,60.92 253.16,60.92
SLEEVE on IN3 (solid shape): 284.61,44.94 284.61,44.13 284.5,44.03 283.28,44.03 282.73,44.59 282.73,44.89 282.9,45.07 284.48,45.07
SLEEVE_R on BOTTOM (solid shape): 289.46,44.14 291.36,44.14 291.49,44.02 291.49,43.44 293.52,41.41 293.52,40.97 291.87,40.97 291.81,41.03 291.81,41.41 290.09,43.13 288.48,43.13 287.47,44.14 285.72,44.14 285.61,44.26 285.61,45.02 285.69,45.1 288.5,45.1
SNB_+1VALWP on TOP (solid shape): 160.33,81.48 160.33,80.52 160.27,80.46 157.33,80.46 157.24,80.54 157.24,81.23 157.37,81.35 158.43,81.35 158.61,81.53 160.29,81.53
SNUB_CHG1 on TOP (solid shape): 40.98,69.99 41.36,69.61 41.36,67.83 40.35,67.83 40.35,69.61 40.09,69.86 40.09,70.5 40.98,70.5
SNUB_CHG2 on TOP (solid shape): 52.86,64.65 53.11,64.4 53.55,64.4 53.55,62.75 52.41,62.75 51.97,63.19 51.97,65.42 52.86,65.42
SW_+1VALWP on TOP (solid shape): 160.34,84.18 160.34,83.04 160.03,82.73 157.11,82.73 157,82.84 157,83.14 157.14,83.28 157.44,83.28 157.47,83.32 157.47,84.24 157.53,84.3 160.23,84.3
SW_+1VALWP on BOTTOM (solid shape): 160.2,84.03 160.2,81.34 160.15,81.29 158.27,81.29 157.06,82.5 156.04,82.5 156.04,83.64 157.14,83.64 157.58,84.08 160.15,84.08
UG1_ISL88738 on TOP (solid shape): 48.6,71.64 48.6,70.24 48.47,70.11 47.59,70.11 47.46,70.24 47.46,71.64 47.65,71.83 48.41,71.83
UG1_ISL88738 on TOP (solid shape): 57.58,60.62 57.58,60.29 57.3,60.01 57.3,59.57 57.22,59.5 57.22,58.68 57.17,58.63 57.07,58.63 57.02,58.68 57.02,59.52 57,59.55 57,59.73 56.84,59.88 56.84,60.36 57.2,60.72 57.48,60.72
UG1_ISL88738 on IN1 (solid shape): 48.56,70.47 48.56,69.38 48.46,69.28 47.62,69.28 47.5,69.4 47.5,70.47 47.62,70.6 48.44,70.6
UG1_ISL88738 on IN1 (solid shape): 57.58,61.25 57.58,60.41 57.3,60.13 57.3,59.88 57.15,59.73 56.79,59.73 56.62,59.9 56.62,61.33 56.92,61.63 57.2,61.63
N16775433 on TOP (solid shape): 68.48,69.86 68.48,68.53 66.95,68.53 66.83,68.65 66.83,70.5 67.84,70.5
N16775517 on BOTTOM (solid shape): 66.67,68.91 66.67,68.57 66.06,67.96 64.1,67.96 64.1,68.83 64.11,68.84 64.72,68.84 64.86,68.71 65.86,68.71 66.13,68.97 66.61,68.97
N16783014 on TOP (solid shape): 157.99,80 157.99,78.03 156.61,76.66 155.85,76.66 155.73,76.78 155.73,77.67 155.83,77.77 155.83,77.9 156.11,78.18 156.11,79.46 156.69,79.46 156.95,79.21 157.38,79.21 157.5,79.34 157.5,80.02 157.96,80.02
N16783014 on BOTTOM (solid shape): 156.68,77.48 156.68,76.08 156.36,75.77 155.66,75.77 155.54,75.89 155.54,76.4 155.73,76.59 155.73,77.54 155.85,77.67 156.49,77.67
N16783223 on BOTTOM (solid shape): 187.03,57.22 187.03,56.11 186.89,55.97 186.1,55.97 186.05,56.02 186.05,56.6 186.33,56.88 186.33,57.16 186.52,57.35 186.9,57.35
N16784595 on BOTTOM (solid shape): 158.01,71.32 157.47,71.32 156.97,70.83 155.93,70.83 155.93,71.44 156.64,71.44 156.64,71.44 156.79,71.44 157.12,71.77 157.12,71.95 157.12,71.96 158.01,71.96
N16784799 on BOTTOM (solid shape): 188.06,51.17 188.06,50.56 185.95,50.56 185.95,51.19 188.03,51.19
N17370862 on BOTTOM (solid shape): 46,112.28 46,111.64 45.68,111.33 45.68,109.55 45.62,109.48 44.16,109.48 44.09,109.55 44.09,109.99 44.16,110.06 44.79,110.06 45.05,110.31 45.05,111.77 45.68,112.41 45.87,112.41
N17371029 on BOTTOM (solid shape): 48.66,121.26 48.6,121.2 48.55,121.12 48.51,121.07 48.48,121 48.46,120.84 48.52,120.69 48.52,119.1 47.83,118.4 47.62,118.4 47.51,118.51 47.51,119.24 47.59,119.32 47.59,120.91 47.27,121.23 47.27,121.87 48.66,121.87
N17802718 on TOP (solid shape): 48.89,103.36 48.89,102.66 48.09,101.86 44.7,101.86 44.58,101.99 44.58,102.55 44.6,102.55 44.6,102.56 47.39,102.56 48.3,103.47 48.78,103.47
N18278782 on TOP (solid shape): 58.67,62.32 56.62,62.32 56.62,62.95 58.67,62.95
N39469998 on TOP (solid shape): 61.49,112.48 61.47,112.46 59.79,112.46 59.64,112.61 59.64,113.22 59.79,113.37 61.49,113.37
N39473185 on BOTTOM (solid shape): 60.59,91.04 60.59,89.83 60.26,89.5 59.9,89.5 59.78,89.37 59.78,88.73 58.89,88.73 58.89,89.37 59.35,89.83 60.06,89.83 60.39,90.16 60.39,91.04 60.44,91.1 60.54,91.1
N39473187 on BOTTOM (solid shape): 61,91.06 61,88.72 60.11,88.72 60.11,89.36 60.39,89.36 60.78,89.75 60.78,91.04 60.83,91.1 60.96,91.1
N39473189 on BOTTOM (solid shape): 60.98,87.34 58.9,87.34 58.9,87.97 60.98,87.97
N39473270 on BOTTOM (solid shape): 54.13,110.96 54.13,110.55 54.66,110.02 55.5,110.02 55.55,109.97 55.55,109.87 55.5,109.82 54.2,109.82 53.82,110.2 53.31,110.2 53.29,110.22 53.29,111.09 54,111.09
N39473272 on BOTTOM (solid shape): 54.18,109.64 55.5,109.64 55.55,109.59 55.55,109.46 55.5,109.41 54.58,109.41 54.15,108.98 53.31,108.98 53.31,109.87 53.95,109.87
N39473274 on BOTTOM (solid shape): 52.55,108.98 51.89,108.98 51.89,111.09 52.55,111.09
N132000604 on TOP (solid shape): 62.51,56.4 61.87,56.4 61.87,58.51 62.51,58.51

Small or netless copper shapes (teardrops, artwork), in the pictures only: 191 on TOP, 90 on BOTTOM, 4 on GND1, 1 on IN1, 1 on IN2, 3 on IN3, 4 on GND2

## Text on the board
Ref Des/Silkscreen Bottom: REV:A00 | PWA P/N: | ALL RIGHT RESERVED | PWB 6KV79 | COPYRIGHT 2016 | H25 | 9 | M2X3 | H26 | 10 | 11 | FAN CABLE | SPEAKER | EDP CABLE | DIMM | DDR4 | CABLE | BATTERY | TP | USH | RTC | LED | DC-IN | 2 | 3 | 4 | 5 | 6 | 1 | 7 | 8 | WLAN | WIGIG | BT | WWAN
User.Comments: LA-E122P | 2016-11-08 | 2017-11-08 | CAZ10 | Moniika_song | GND | +VCC_GT | +VCC_SA | +VCC_CORE | +3.3V_ALW | +3.3V_RUN | +1.0VS_VCCIO | +3.3V_ALW_PCH | +1.0V_PRIM | +5V_ALW | +5V_RUN | GNDA
BODY_CENTER: L7 | L8 | TOP | GND1 | IN1 | VCC | IN2 | IN3 | GND2 | BOT
User.38: L5/L7
User.39: FIGURE | SIZE | 8.0 | 16.0 | 20.0 | 22.0 | 28.0 | 35.0 | 39.0 | 102.0 | 122.0 | 126.0 | 134.0 | 138.0 | 150.0 | 30.0 | 31.0 | 43.0 | 45.0 | 63.0 | 65.0 | 71.0 | 91.0 | 47.0x16.0 | 55.0x24.0 | 55.0x28.0 | 57.0x24.0 | 63.0x24.0 | 63.0x31.0 | 67.0x28.0 | 94.0x28.0 | 94.0x43.0 | 37.0x28.0 | 106.0x91.0 | DRILL CHART: TOP to BOTTOM | ALL UNITS ARE IN MILS | TOLERANCE | +3.0/-3.0 | +2.0/-2.0 | PLATED | NON-PLATED | QTY | 5412 | 12 | 33 | 19 | 18 | 10 | 5 | 2 | 4 | 1 | 3 | 7
